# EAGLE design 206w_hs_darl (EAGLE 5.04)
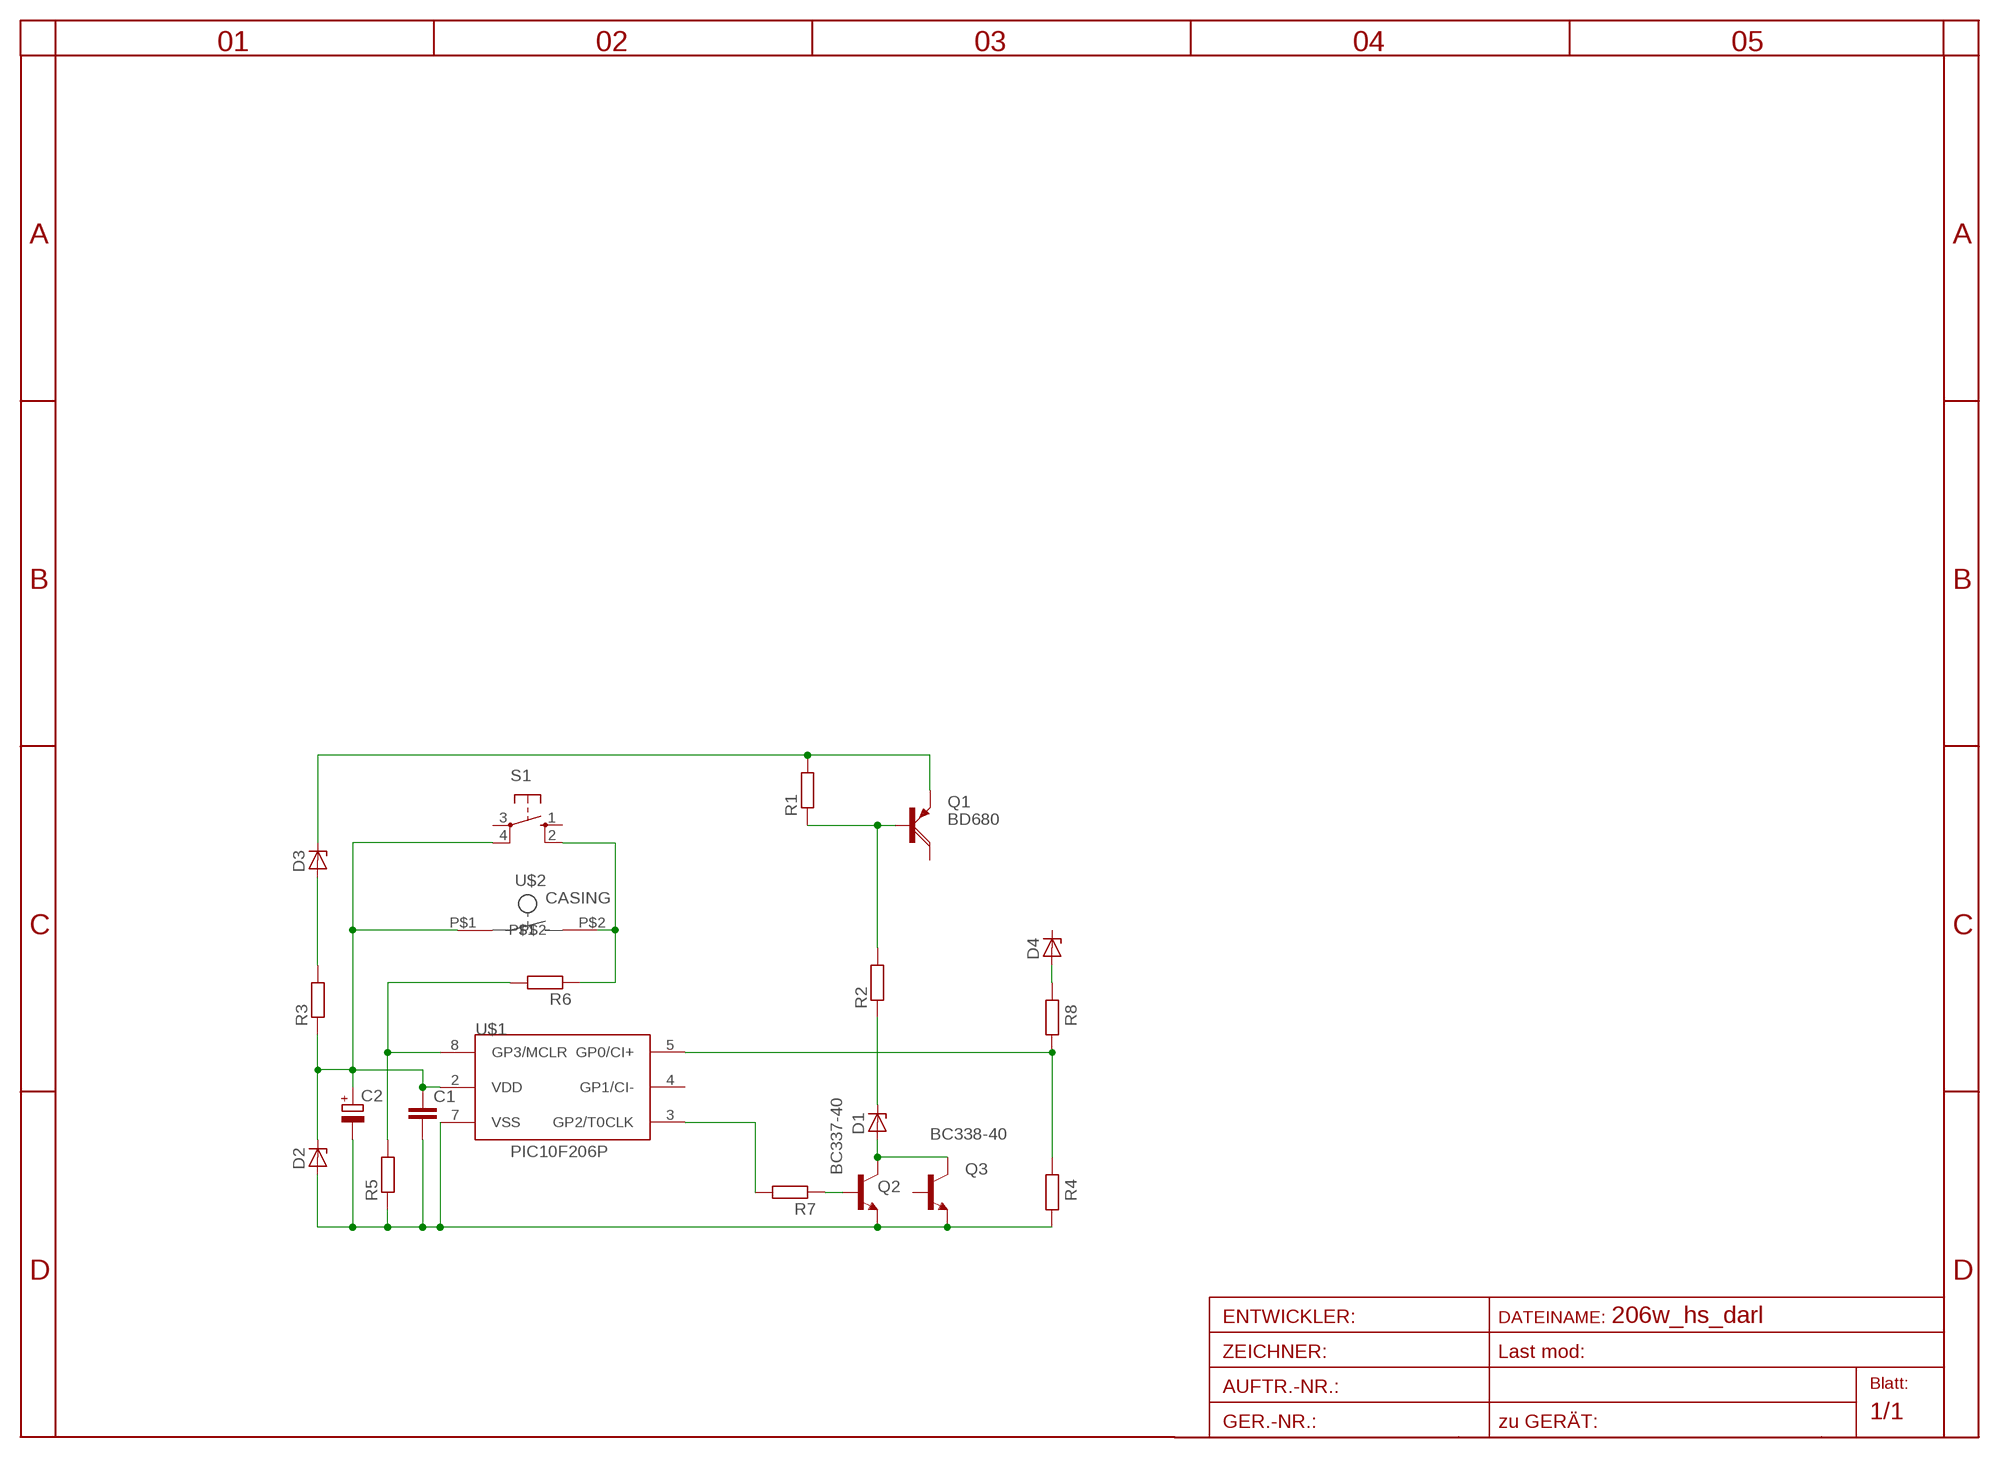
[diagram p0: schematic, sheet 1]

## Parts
C1  C-EU025-025X050  [C025-025X050]
C2  CPOL-EUE2.5-5  [E2,5-5]
D1  ZENER-DIODEDO41-20  [DO41-20]
D2  ZENER-DIODEZD-7.5  [ZDIO-7.5]
D3  ZENER-DIODEZD-7.5  [ZDIO-7.5]
D4  ZENER-DIODEZD-7.5  [ZDIO-7.5]
Q1  BD680  [TO126AV]
Q2  BC337-40  [TO92]
Q3  BC338-40  [TO92-EBC]
R1  R-EU_0204/7  [0204/7]
R2  R-EU_0204/7  [0204/7]
R3  R-EU_0204/7  [0204/7]
R4  R-EU_0204/7  [0204/7]
R5  R-EU_0204/7  [0204/7]
R6  R-EU_0204/7  [0204/7]
R7  R-EU_0204/7  [0204/7]
R8  R-EU_0204/7  [0204/7]
S1  10-XX  [B3F-10XX]
U$1  PIC10F206P  [DIL8]
U$2  CASING  [CASING]

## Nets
GND: C1.2 C2.- D2.A Q2.1(E) Q3.E R4.1 R5.1 U$1.7(VSS)
N$1: D4.A R8.2
N$2: C1.1 C2.+ D2.C R3.1 S1.4(P1) U$1.2(VDD) U$2.P$1
N$3: D3.A R3.2
N$5: R5.2 R6.2 U$1.8(GP3/MCLR)
N$7: R6.1 S1.2(S1) U$2.P$2
N$9: R7.2 U$1.3(GP2/T0CLK)
N$10: Q2.2(B) R7.1
N$11: D1.A Q2.3(C) Q3.C
N$12: D1.C R2.1
N$13: Q1.B R1.1 R2.2
N$14: R4.2 R8.1 U$1.5(GP0/CI+)
V60: D3.C Q1.E R1.2
Unconnected: D4.C Q1.C Q3.B S1.1(S) S1.3(P) U$1.4(GP1/CI-)

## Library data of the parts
C1 = rcl:C-EU: CAPACITOR, European symbol
C2 = rcl:CPOL-EU: POLARIZED CAPACITOR, European symbol
D1-D4 = diode-1:ZENER-DIODE: Z-Diode
Q1 = transistor-power:BD680: PNP DARLINGTON TRANSISTOR
Q2 = transistor-npn:BC337*: NPN Transistor
Q3 = transistor-npn:BC338*: NPN Transistor
R1-R8 = rcl:R-EU_: RESISTOR, European symbol
S1 = switch-omron:10-XX: OMRON SWITCH
U$1 = microchip-5:PIC10F2*: uPC nW 0,25/0,5k Program Flash memory Comparator
U$2 = button:CASING

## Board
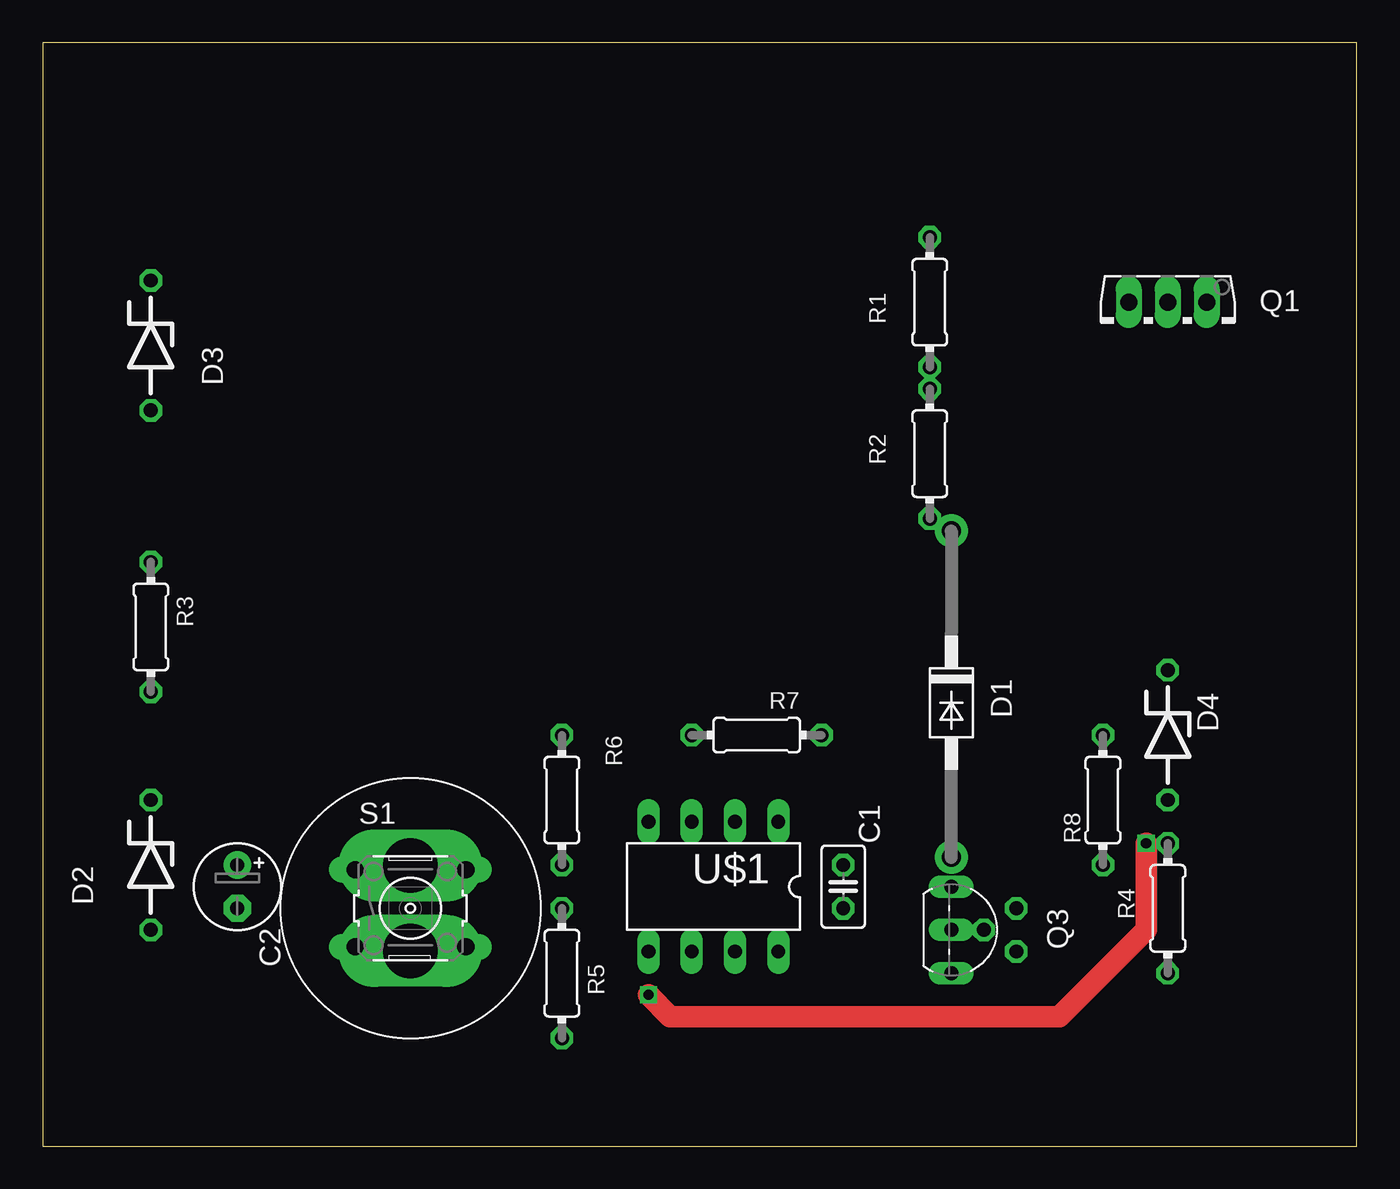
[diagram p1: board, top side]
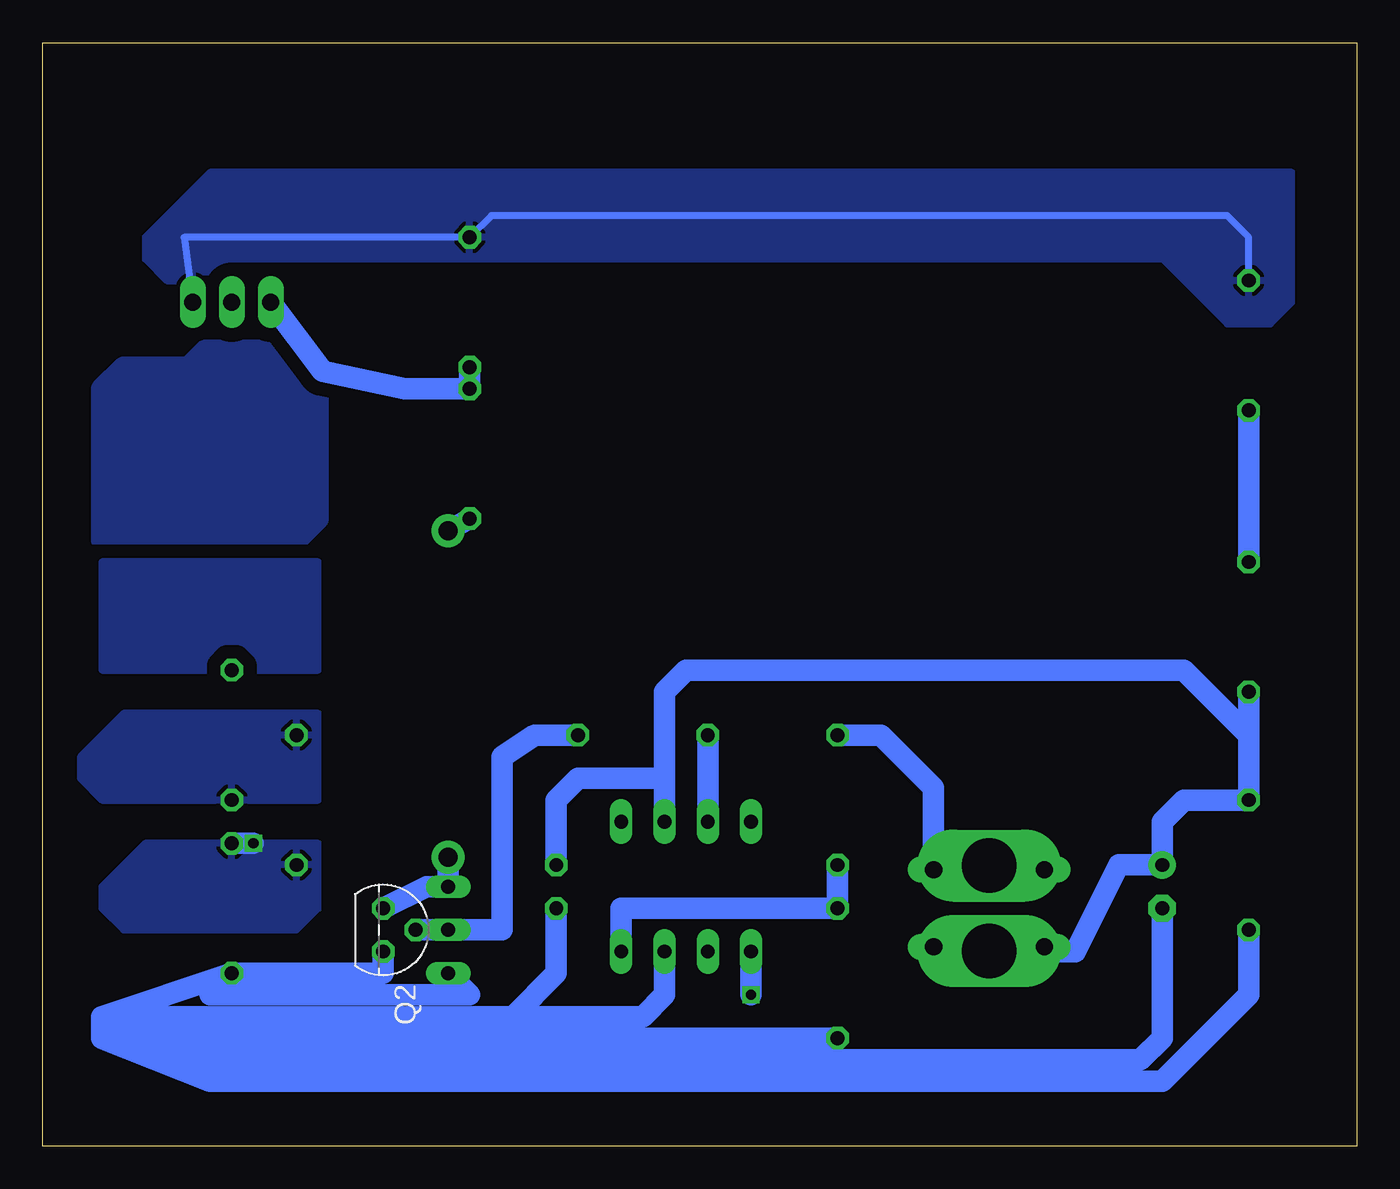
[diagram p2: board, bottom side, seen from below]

Size 77.14 x 64.76 mm. Coordinates in mm from the lower left corner, seen from the top.
Outline: 0,0 77.14,0 77.14,64.76 0,64.76 0,0
Copper layers (1*16): Top 0.035mm / dielectric 1.5mm / Bottom 0.035mm
Design rules "default": minimum track width 10mil, minimum drill 24mil, track to track 8mil, track to pad 8mil, pad to pad 8mil, via to via 8mil, smd to smd 8mil, copper to edge 40mil, drill to drill 8mil, minimum pad ring 10mil, minimum via ring 8mil, stop-mask expansion 4mil, vias tented up to drill 0mil, thermal gap 10mil

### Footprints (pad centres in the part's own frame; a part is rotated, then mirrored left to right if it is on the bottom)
C025-025X050 = drill 0.813 octagon: 1 -1.27,0; 2 1.27,0
E2,5-5 = drill 0.813 pad 1.6 round: + -1.27,0 | drill 0.813 pad 1.6 octagon: - 1.27,0
DO41-20 = drill 1.118 pad 1.93 round: A 9.08,0; C -10.08,0
ZDIO-7.5 = drill 0.813 octagon: A 3.81,0; C -3.81,0
TO126AV = drill 1.016 long: B 2.286,-1.27; C 0,-1.27; E -2.286,-1.27
TO92 = drill 0.813 octagon: 1 1.27,0; 2 0,1.905; 3 -1.27,0
TO92-EBC = drill 0.813 long: B 0,-1.27; C -2.54,-1.27; E 2.54,-1.27
0204/7 = drill 0.813 octagon: 1 -3.81,0; 2 3.81,0
B3F-10XX = drill 1.016 long: 1 -3.251,2.261; 2 3.251,2.261; 3 -3.251,-2.261; 4 3.251,-2.261
DIL8 = drill 0.813 long: 1 -3.81,-3.81; 2 -1.27,-3.81; 3 1.27,-3.81; 4 3.81,-3.81; 5 3.81,3.81; 6 1.27,3.81; 7 -1.27,3.81; 8 -3.81,3.81
CASING = drill 3.2 pad 3.81 long: P$1 -2.5,0; P$2 2.5,0

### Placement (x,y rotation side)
C1  46.99,15.24 270 top
C2  11.43,15.24 270 top
D1  53.34,26.04 270 top
D2  6.35,16.51 270 top
D3  6.35,46.99 270 top
D4  66.04,24.13 270 top
Q1  66.04,48.26 180 top
Q2  57.15,12.7 270 bottom
Q3  54.61,12.7 270 top
R1  52.07,49.53 90 top
R2  52.07,40.64 90 top
R3  6.35,30.48 90 top
R4  66.04,13.97 90 top
R5  30.48,10.16 90 top
R6  30.48,20.32 270 top
R7  41.91,24.13 180 top
R8  62.23,20.32 90 top
S1  21.59,13.97 0 top
U$1  39.37,15.24 180 top
U$2  21.59,13.97 90 top

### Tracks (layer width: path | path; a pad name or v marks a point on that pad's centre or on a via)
GND
  Bottom 1.27: D2.A 6.35,8.89 11.43,3.81 67.31,3.81 73.66,6.35 73.66,7.62 | 73.66,7.62 R4.1 | R4.1 57.15,10.16 Q2.1 | C2.- 11.43,6.35 12.7,5.08 67.31,5.08 73.66,7.62 | 73.66,7.62 68.58,6.35 R5.1 | U$1.7 40.64,8.89 41.91,7.62 49.53,7.62 | 73.66,7.62 49.53,7.62 | Q3.E 52.07,8.89 67.31,8.89 R4.1 | C1.2 46.99,10.16 49.53,7.62
N$1
  pour Bottom (isolate 0.813, rank 3): 60.96,25.4 72.39,25.4 74.93,22.86 74.93,21.59 73.66,20.32 60.96,20.32
N$2
  Bottom 1.27: 24.56,11.43 16.51,11.43 13.97,16.51 C2.+ 11.43,19.05 10.16,20.32 D2.C 6.35,24.13 | 24.56,11.43 S1.4 | 24.56,11.43 21.63,11.43 U$2.P$1 | 40.64,21.59 40.64,26.67 39.37,27.94 10.16,27.94 6.35,24.13 | 40.64,21.59 U$1.2 | C1.1 46.99,20.32 45.72,21.59 40.64,21.59 | 6.35,24.13 R3.1
N$3
  Bottom 1.27: R3.2 D3.A
N$4
  pour Bottom (isolate 0.813, rank 5): 66.04,48.26 64.77,46.99 63.5,46.99 60.96,44.45 60.96,36.83 62.23,35.56 73.66,35.56 73.66,44.45 72.39,45.72 68.58,45.72
N$5
  Bottom 1.27: U$1.8 43.18,13.97 R5.2 R6.2
N$6
  pour Bottom (isolate 0.813, rank 4): 60.96,34.29 73.66,34.29 73.66,27.94 60.96,27.94
N$7
  Bottom 1.27: R6.1 27.94,24.13 24.84,21.03 S1.2 21.83,16.23 U$2.P$2
N$9
  Bottom 1.27: U$1.3 R7.2
N$10
  Bottom 1.27: R7.1 48.26,24.13 50.16,22.86 50.16,12.7 Q2.2
N$11
  Bottom 1.27: Q2.3 54.61,15.24 Q3.C D1.A
N$12
  Bottom 1.27: R2.1 D1.C
N$13
  Bottom 1.27: Q1.B 60.71,45.47 55.88,44.45 R2.2 R1.1
N$14  (via drill 0.6)
  Top 1.27: v35.56,8.89 36.83,7.62 59.69,7.62 64.77,12.7 v64.77,17.78
  Bottom 1.27: v35.56,8.89 U$1.5 | v64.77,17.78 R4.2
  pour Bottom (isolate 0.813, rank 3): 60.96,17.78 71.12,17.78 73.66,15.24 73.66,13.97 72.39,12.7 62.23,12.7 60.96,13.97
V60
  Bottom 0.406: D3.C 6.35,53.34 7.62,54.61 50.8,54.61 R1.2 68.83,53.34 Q1.E
  pour Bottom (isolate 0.813, rank 5): 3.81,57.15 67.31,57.15 71.12,53.34 71.12,52.07 69.85,50.8 67.31,50.8 66.04,52.07 11.43,52.07 7.62,48.26 5.08,48.26 3.81,49.53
